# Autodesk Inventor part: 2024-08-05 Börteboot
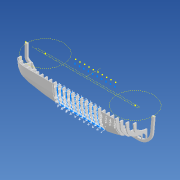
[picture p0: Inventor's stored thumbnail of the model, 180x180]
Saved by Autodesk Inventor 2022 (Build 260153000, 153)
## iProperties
Created: 2024-08
Part Number: 2024-08-05 Börteboot
Material: Generisch
Document SubType Name: Sheet Metal
Designer: i3meg
Density: 1 g/cm^3
Sheet Metal Rule: Standard_mm
Appearance: Vorgabe
Author: i3meg
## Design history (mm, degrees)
derived "2024-08-05 Börteboot.iam"
sketch "Skizze12"
  geometry: L1 (16, 30)-(12, 0) reference; L2 (12, 0)-(7.305, -13) reference; L3 (7.305, -13)-(-3.874, -24) reference; L4 (-3.874, -24)-(-19, -32) reference; L5 (16, 30)-(18, 30); L6 (18, 30)-(14.95, -0.547); L7 (14.95, -0.547)-(13.966, -0.365); L8 (13.966, -0.365)-(10.145, -13.968); L9 (10.145, -13.968)-(9.198, -13.646); L10 (9.198, -13.646)-(-1.833, -26.198); L11 (-1.833, -26.198)-(-2.513, -25.465); L12 (-2.513, -25.465)-(-17.597, -34.652); L13 (-49.5, -37.189)-(-49.5, -40.189); L14 (-49.5, -40.189)-(-47.5, -40.189); A1 r 117.777 centre (-11.284, -152.26) between (-17.597, -34.652) and (-47.5, -40.189); 1 further point
  constraints: 20 end point, 2 horizontal, 2 point on circle, 1 centre point, 1 vertical, 1 other
  dimensions: "d71" = 2 distance of L1.start L5.end; "d72" = 3 distance of L6.end L1.end; "d73" = 2 distance of L7.end L1.end; "d74" = 3 distance of L2.end L8.end; "d75" = 2 distance of L9.end L2.end; "d76" = 3 distance of L3.end L10.end; "d77" = 2 distance of L11.end L3.end; "d78" = 3 distance of L12.end L4.end; "d79" = 3 distance of L13.start L13.end; "d494" = 2 distance of L13.end L14.end
sketch "Skizze13"
  geometry: L1 (16, 35)-(12, 0) reference; L2 (12, 0)-(6, -17) reference; L3 (6, -17)-(-6.612, -32) reference; L4 (-6.612, -32)-(-25, -44) reference; L5 (16, 35)-(18, 35); L6 (18, 35)-(14.981, -0.341); L7 (14.981, -0.341)-(13.987, -0.227); L8 (13.987, -0.227)-(8.768, -18.156); L9 (8.768, -18.156)-(7.801, -17.87); L10 (7.801, -17.87)-(-4.671, -34.287); L11 (-4.671, -34.287)-(-5.623, -33.738); L12 (-5.623, -33.738)-(-23.89, -46.787); L13 (-65.5, -57.331)-(-65.5, -60.331); L14 (-65.5, -60.331)-(-63.5, -60.331); A1 r 220.96 centre (27.472, -261.695) between (-23.89, -46.787) and (-63.5, -60.331); 1 further point
  constraints: 20 end point, 2 point on circle, 1 centre point, 1 horizontal, 1 other
  dimensions: "d80" = 2 distance of L1.start L5.end; "d81" = 2 distance of L1.end L7.end; "d82" = 3 distance of L1.end L6.end; "d83" = 2 distance of L2.end L9.end; "d84" = 3 distance of L2.end L8.end; "d85" = 2 distance of L3.end L11.end; "d86" = 3 distance of L3.end L10.end; "d87" = 3 distance of L4.end L12.end; "d88" = 3 distance of L13.start L13.end; "d495" = 2 distance of L13.end L14.end
sketch "Skizze14"
  geometry: L1 (16, 40)-(12, 1) reference; L2 (12, 1)-(6, -17) reference; L3 (6, -17)-(-6, -34) reference; L4 (-6, -34)-(-24, -48) reference; L5 (0, 40)-(16, 40) reference; L6 (16, 40)-(18, 40); L7 (18, 40)-(14.984, 0.694); L8 (14.984, 0.694)-(13.99, 0.796); L9 (13.99, 0.796)-(8.846, -17.949); L10 (8.846, -17.949)-(7.897, -17.632); L11 (7.897, -17.632)-(-3.549, -35.73); L12 (-3.549, -35.73)-(-4.366, -35.153); L13 (-4.366, -35.153)-(-22.939, -50.806); L14 (-71.5, -66.872)-(-71.5, -69.872); L15 (-71.5, -69.872)-(-69.5, -69.872); A1 r 153.896 centre (11.315, -200.842) between (-22.939, -50.806) and (-69.5, -69.872); 1 further point
  constraints: 20 end point, 2 horizontal, 2 point on circle, 1 centre point, 1 vertical, 1 other
  dimensions: "d93" = 2 distance of L1.start L6.end; "d94" = 3 distance of L14.start L14.end; "d95" = 3 distance of L4.end L13.end; "d96" = 2 distance of L1.end L8.end; "d97" = 2 distance of L2.end L10.end; "d98" = 3 distance of L1.end L7.end; "d99" = 3 distance of L2.end L9.end; "d100" = 2 distance of L3.end L12.end; "d101" = 3 distance of L3.end L11.end; "d496" = 2 distance of L14.end L15.end
sketch "Skizze19"
  geometry: L1 (16, 40)-(12, -2) reference; L2 (12, -2)-(5, -20) reference; L3 (5, -20)-(-6, -38) reference; L4 (-6, -38)-(-23, -53) reference; L5 (16, 40)-(18, 40); L6 (18, 40)-(14.986, -2.284); L7 (14.986, -2.284)-(13.991, -2.19); L8 (13.991, -2.19)-(7.745, -21.211); L9 (7.745, -21.211)-(6.775, -20.923); L10 (6.775, -20.923)-(-3.62, -39.826); L11 (-3.62, -39.826)-(-4.6, -39.428); L12 (-4.6, -39.428)-(-21.466, -55.578); L13 (-73.5, -75.618)-(-73.5, -78.618); L14 (-73.5, -78.618)-(-71.5, -78.618); A1 r 207.905 centre (39.712, -254.278) between (-21.466, -55.578) and (-71.5, -78.618); 1 further point
  constraints: 20 end point, 2 horizontal, 2 point on circle, 1 centre point, 1 vertical, 1 other
  dimensions: "d114" = 2 distance of L1.start L5.end; "d115" = 3 distance of L13.start L13.end; "d116" = 2 distance of L1.end L7.end; "d117" = 3 distance of L1.end L6.end; "d118" = 2 distance of L2.end L9.end; "d119" = 3 distance of L2.end L8.end; "d120" = 2 distance of L3.end L11.end; "d121" = 3 distance of L3.end L10.end; "d122" = 3 distance of L4.end L12.end; "d497" = 2 distance of L13.end L14.end
sketch "Skizze23"
  geometry: L1 (16, 40)-(12, -3) reference; L2 (12, -3)-(6, -22) reference; L3 (6, -22)-(-5, -41) reference; L4 (-5, -41)-(-20, -57) reference; L5 (-73.5, -76.921)-(-73.5, -80.121); L6 (16, 40)-(18, 40); L7 (18, 40)-(14.986, -3.289); L8 (14.986, -3.289)-(13.988, -3.219); L9 (13.988, -3.219)-(8.888, -22.814); L10 (8.888, -22.814)-(7.919, -22.562); L11 (7.919, -22.562)-(-2.341, -42.39); L12 (-2.341, -42.39)-(-3.165, -41.796); L13 (-3.165, -41.796)-(-18.949, -59.81); L14 (-73.5, -80.121)-(-71.5, -80.121); A1 r 141.801 centre (4.877, -199.595) between (-18.949, -59.81) and (-71.5, -80.121); 1 further point
  constraints: 20 end point, 2 horizontal, 2 perpendicular, 2 point on circle, 1 centre point, 1 vertical, 1 other
  dimensions: "d142" = 3.2 distance of L5.start L5.end; "d143" = 2 distance of L1.start L6.end; "d144" = 2 distance of L1.end L8.end; "d145" = 3 distance of L1.end L7.end; "d146" = 2 distance of L2.end L10.end; "d147" = 3 distance of L2.end L9.end; "d148" = 2 distance of L3.end L12.end; "d149" = 3 distance of L3.end L11.end; "d150" = 3 distance of L13.end L4.end; "d498" = 2 distance of L5.end L14.end
sketch "Skizze24"
  geometry: L1 (16, 40)-(12, -4) reference; L2 (12, -4)-(6.5, -24) reference; L3 (6.5, -24)-(-4, -44) reference; L4 (-4, -44)-(-19, -61) reference; L5 (0, 40)-(16, 40) reference; L6 (16, 40)-(18, 40); L7 (18, 40)-(14.988, -4.272); L8 (14.988, -4.272)-(13.992, -4.181); L9 (13.992, -4.181)-(9.359, -24.909); L10 (9.359, -24.909)-(8.369, -24.713); L11 (8.369, -24.713)-(-1.344, -45.395); L12 (-1.344, -45.395)-(-2.229, -44.93); L13 (-2.229, -44.93)-(-17.749, -63.727); L14 (-73.5, -77.771)-(-73.5, -80.771); L15 (-73.5, -80.771)-(-71.5, -80.771); A1 r 219.794 centre (17.847, -277.683) between (-19, -61) and (-73.5, -77.771) reference; A2 r 202.647 centre (16.032, -263.538) between (-17.749, -63.727) and (-71.5, -80.771); 1 further point
  constraints: 20 end point, 2 horizontal, 2 point on circle, 1 centre point, 1 vertical
  dimensions: "d161" = 2 distance of L1.start L6.end; "d166" = 2 distance of L1.end L8.end; "d167" = 3 distance of L1.end L7.end; "d169" = 2 distance of L2.end L10.end; "d170" = 3 distance of L2.end L9.end; "d173" = 2 distance of L3.end L12.end; "d174" = 3 distance of L3.end L11.end; "d175" = 3 distance of L4.end L13.end; "d176" = 3 distance of L14.start L14.end; "d499" = 2 distance of L14.end L15.end
sketch "Skizze25"
  geometry: L1 (-2, -46)-(-18, -64) reference; L2 (7, -26)-(-2, -46) reference; L3 (12, -5)-(7, -26) reference; L4 (16, 40)-(12, -5) reference; L5 (16, 40)-(18, 40); L6 (18, 40)-(14.978, -5.364); L7 (14.978, -5.364)-(13.992, -5.177); L8 (13.992, -5.177)-(9.918, -26.695); L9 (9.918, -26.695)-(8.945, -26.465); L10 (8.945, -26.465)-(0.736, -47.231); L11 (0.736, -47.231)-(-0.176, -46.821); L12 (-0.176, -46.821)-(-16.767, -66.735); L13 (-73.5, -77.91)-(-73.5, -80.91); L14 (-73.5, -80.91)-(-71.5, -80.91); A1 r 433.619 centre (-150.935, 348.739) between (-73.5, -77.91) and (-18, -64) reference; A2 r 310.184 centre (-121.575, 225.206) between (-71.5, -80.91) and (-16.767, -66.735); 1 further point
  constraints: 20 end point, 2 horizontal, 2 point on circle, 1 centre point, 1 perpendicular, 1 vertical
  dimensions: "d189" = 2 distance of L4.start L5.end; "d190" = 3 distance of L13.start L13.end; "d191" = 2 distance of L3.start L7.end; "d192" = 3 distance of L3.start L6.end; "d193" = 2 distance of L2.start L9.end; "d194" = 3 distance of L2.start L8.end; "d195" = 2 distance of L1.start L11.end; "d196" = 3 distance of L1.start L10.end; "d197" = 3 distance of L1.end L12.end; "d500" = 2 distance of L13.end L14.end
sketch "Skizze27"
  geometry: L1 (16, 40)-(12, -6) reference; L2 (12, -6)-(7.5, -27) reference; L3 (7.5, -27)-(-1, -48) reference; L4 (-1, -48)-(-18, -66) reference; L5 (16, 40)-(18, 40); L6 (18, 40)-(14.981, -6.337); L7 (14.981, -6.337)-(13.992, -6.173); L8 (13.992, -6.173)-(10.417, -27.702); L9 (10.417, -27.702)-(9.43, -27.524); L10 (9.43, -27.524)-(1.773, -49.144); L11 (1.773, -49.144)-(0.854, -48.75); L12 (0.854, -48.75)-(-15.819, -68.06); L13 (-73.5, -77.945)-(-73.5, -80.945); A1 r 279.676 centre (-104.292, 200.031) between (-73.5, -77.945) and (-18, -66) reference; A2 r 259.061 centre (-100.77, 176.677) between (-73.5, -80.945) and (-15.819, -68.06); 1 further point
  constraints: 18 end point, 2 point on circle, 1 centre point, 1 horizontal, 1 perpendicular, 1 vertical
  dimensions: "d198" = 2 distance of L1.start L5.end; "d200" = 2 distance of L1.end L7.end; "d201" = 3 distance of L1.end L6.end; "d202" = 2 distance of L2.end L9.end; "d203" = 3 distance of L2.end L8.end; "d204" = 2 distance of L3.end L11.end; "d205" = 3 distance of L3.end L10.end; "d206" = 3 distance of L4.end L12.end; "d207" = 3 distance of L13.start L13.end
sketch "Skizze28"
  geometry: L1 (12, -7)-(16, 40) reference; L2 (8, -28)-(12, -7) reference; L3 (0, -49)-(8, -28) reference; L4 (-16, -67)-(0, -49) reference; L5 (-73.5, -77.992)-(-73.5, -80.992); L6 (16, 40)-(18, 40); L7 (18, 40)-(14.947, -7.561); L8 (14.947, -7.561)-(13.965, -7.374); L9 (13.965, -7.374)-(10.76, -29.176); L10 (10.76, -29.176)-(9.795, -28.883); L11 (9.795, -28.883)-(2.778, -50.133); L12 (2.778, -50.133)-(1.822, -49.824); L13 (1.822, -49.824)-(-13.372, -68.446); A1 r 171.355 centre (-76.452, 93.337) between (-73.5, -77.992) and (-16, -67) reference; A2 r 176.524 centre (-78.941, 95.448) between (-73.5, -80.992) and (-13.372, -68.446); 1 further point
  constraints: 18 end point, 2 point on circle, 1 centre point, 1 horizontal, 1 vertical
  dimensions: "d224" = 3 distance of L5.start L5.end; "d225" = 2 distance of L1.end L6.end; "d226" = 2 distance of L1.start L8.end; "d227" = 3 distance of L1.start L7.end; "d228" = 2 distance of L2.start L10.end; "d229" = 3 distance of L2.start L9.end; "d230" = 2 distance of L3.start L12.end; "d231" = 3 distance of L3.start L11.end; "d232" = 3 distance of L4.start L13.end
sketch "Skizze37"
  geometry: L1 (12, -7)-(16, 40) reference; L2 (8, -28)-(12, -7) reference; L3 (0, -49)-(8, -28) reference; L4 (-16, -67)-(0, -49) reference; L5 (-73.5, -77.992)-(-73.5, -80.992); L6 (16, 40)-(0, 40) reference; L7 (16, 40)-(18, 40); L8 (18, 40)-(14.985, -7.302); L9 (14.985, -7.302)-(13.993, -7.17); L10 (13.993, -7.17)-(10.905, -28.749); L11 (10.905, -28.749)-(9.955, -28.421); L12 (9.955, -28.421)-(2.818, -50.028); L13 (2.818, -50.028)-(1.868, -49.714); L14 (1.868, -49.714)-(-13.461, -68.598); A1 r 171.355 centre (-76.452, 93.337) between (-73.5, -77.992) and (-16, -67) reference; A2 r 170.875 centre (-77.466, 89.837) between (-73.5, -80.992) and (-13.461, -68.598); 1 further point
  constraints: 18 end point, 2 point on circle, 1 centre point, 1 horizontal, 1 perpendicular, 1 vertical
  dimensions: "d286" = 3 distance of L5.start L5.end; "d287" = 2 distance of L1.end L7.end; "d288" = 2 distance of L1.start L9.end; "d289" = 3 distance of L1.start L8.end; "d290" = 2 distance of L2.start L11.end; "d291" = 3 distance of L2.start L10.end; "d292" = 2 distance of L3.start L13.end; "d293" = 3 distance of L3.start L12.end; "d294" = 3 distance of L4.start L14.end
sketch "Skizze38"
  geometry: L1 (9.955, -28.421)-(2.818, -50.028); L2 (0, -49)-(8, -28); L3 (2.818, -50.028)-(1.868, -49.714); L4 (1.868, -49.714)-(-13.461, -68.598); L5 (-16, -67)-(0, -49); L6 (-73.5, -77.992)-(-73.5, -80.992); L7 (10.905, -28.749)-(9.955, -28.421); L8 (8, -28)-(12, -7); L9 (13.993, -7.17)-(10.905, -28.749); L10 (14.985, -7.302)-(13.993, -7.17); L11 (16, 40)-(0, 40); L12 (12, -7)-(16, 40); L13 (16, 40)-(18, 40); L14 (18, 40)-(14.985, -7.302); A1 r 170.875 centre (-77.466, 89.837) between (-73.5, -80.992) and (-13.461, -68.598); A2 r 171.355 centre (-76.452, 93.337) between (-73.5, -77.992) and (-16, -67); 1 further point
  constraints: 28 end point, 4 point on circle, 2 centre point, 1 horizontal, 1 perpendicular, 1 vertical
  dimensions: "d295" = 3 distance of L6.start L6.end; "d296" = 2 distance of L11.start L13.end; "d297" = 2 distance of L8.end L9.start; "d298" = 3 distance of L8.end L10.start; "d299" = 2 distance of L2.end L1.start; "d300" = 3 distance of L2.end L7.start; "d301" = 2 distance of L2.start L3.end; "d302" = 3 distance of L2.start L1.end; "d303" = 3 distance of L5.start L4.end
sketch "Skizze39"
  geometry: L1 (9.955, -28.421)-(2.818, -50.028); L2 (0, -49)-(8, -28); L3 (2.818, -50.028)-(1.868, -49.714); L4 (1.868, -49.714)-(-13.461, -68.598); L5 (-16, -67)-(0, -49); L6 (-73.5, -77.992)-(-73.5, -80.992); L7 (10.905, -28.749)-(9.955, -28.421); L8 (8, -28)-(12, -7); L9 (13.993, -7.17)-(10.905, -28.749); L10 (14.985, -7.302)-(13.993, -7.17); L11 (16, 40)-(0, 40); L12 (12, -7)-(16, 40); L13 (16, 40)-(18, 40); L14 (18, 40)-(14.985, -7.302); A1 r 170.875 centre (-77.466, 89.837) between (-73.5, -80.992) and (-13.461, -68.598); A2 r 171.355 centre (-76.452, 93.337) between (-73.5, -77.992) and (-16, -67); 1 further point
  constraints: 28 end point, 4 point on circle, 2 centre point, 1 horizontal, 1 perpendicular, 1 vertical
  dimensions: "d304" = 3 distance of L6.start L6.end; "d305" = 2 distance of L11.start L13.end; "d306" = 2 distance of L8.end L9.start; "d307" = 3 distance of L8.end L10.start; "d308" = 2 distance of L2.end L1.start; "d309" = 3 distance of L2.end L7.start; "d310" = 2 distance of L2.start L3.end; "d311" = 3 distance of L2.start L1.end; "d312" = 3 distance of L5.start L4.end
sketch "Skizze40"
  geometry: L1 (9.955, -28.421)-(2.818, -50.028); L2 (0, -49)-(8, -28); L3 (2.818, -50.028)-(1.868, -49.714); L4 (1.868, -49.714)-(-13.461, -68.598); L5 (-16, -67)-(0, -49); L6 (-73.5, -77.992)-(-73.5, -80.992); L7 (10.905, -28.749)-(9.955, -28.421); L8 (8, -28)-(12, -7); L9 (13.993, -7.17)-(10.905, -28.749); L10 (14.985, -7.302)-(13.993, -7.17); L11 (16, 40)-(0, 40); L12 (12, -7)-(16, 40); L13 (16, 40)-(18, 40); L14 (18, 40)-(14.985, -7.302); A1 r 170.875 centre (-77.466, 89.837) between (-73.5, -80.992) and (-13.461, -68.598); A2 r 171.355 centre (-76.452, 93.337) between (-73.5, -77.992) and (-16, -67); 1 further point
  constraints: 28 end point, 4 point on circle, 2 centre point, 1 horizontal, 1 perpendicular, 1 vertical
  dimensions: "d313" = 3 distance of L6.start L6.end; "d314" = 2 distance of L11.start L13.end; "d315" = 2 distance of L8.end L9.start; "d316" = 3 distance of L8.end L10.start; "d317" = 2 distance of L2.end L1.start; "d318" = 3 distance of L2.end L7.start; "d319" = 2 distance of L2.start L3.end; "d320" = 3 distance of L2.start L1.end; "d321" = 3 distance of L5.start L4.end
sketch "Skizze41"
  geometry: L1 (9.955, -28.421)-(2.818, -50.028); L2 (0, -49)-(8, -28); L3 (2.818, -50.028)-(1.868, -49.714); L4 (1.868, -49.714)-(-13.461, -68.598); L5 (-16, -67)-(0, -49); L6 (-73.5, -77.992)-(-73.5, -80.992); L7 (10.905, -28.749)-(9.955, -28.421); L8 (8, -28)-(12, -7); L9 (13.993, -7.17)-(10.905, -28.749); L10 (14.985, -7.302)-(13.993, -7.17); L11 (16, 40)-(0, 40); L12 (12, -7)-(16, 40); L13 (16, 40)-(18, 40); L14 (18, 40)-(14.985, -7.302); A1 r 170.875 centre (-77.466, 89.837) between (-73.5, -80.992) and (-13.461, -68.598); A2 r 171.355 centre (-76.452, 93.337) between (-73.5, -77.992) and (-16, -67); 1 further point
  constraints: 28 end point, 4 point on circle, 2 centre point, 1 horizontal, 1 perpendicular, 1 vertical
  dimensions: "d322" = 3 distance of L6.start L6.end; "d323" = 2 distance of L11.start L13.end; "d324" = 2 distance of L8.end L9.start; "d325" = 3 distance of L8.end L10.start; "d326" = 2 distance of L2.end L1.start; "d327" = 3 distance of L2.end L7.start; "d328" = 2 distance of L2.start L3.end; "d329" = 3 distance of L2.start L1.end; "d330" = 3 distance of L5.start L4.end
sketch "Skizze42"
  geometry: L1 (9.955, -28.421)-(2.818, -50.028); L2 (0, -49)-(8, -28); L3 (2.818, -50.028)-(1.868, -49.714); L4 (1.868, -49.714)-(-13.461, -68.598); L5 (-16, -67)-(0, -49); L6 (-73.5, -77.992)-(-73.5, -80.992); L7 (10.905, -28.749)-(9.955, -28.421); L8 (8, -28)-(12, -7); L9 (13.993, -7.17)-(10.905, -28.749); L10 (14.985, -7.302)-(13.993, -7.17); L11 (16, 40)-(0, 40); L12 (12, -7)-(16, 40); L13 (16, 40)-(18, 40); L14 (18, 40)-(14.985, -7.302); A1 r 170.875 centre (-77.466, 89.837) between (-73.5, -80.992) and (-13.461, -68.598); A2 r 171.355 centre (-76.452, 93.337) between (-73.5, -77.992) and (-16, -67); 1 further point
  constraints: 28 end point, 4 point on circle, 2 centre point, 1 horizontal, 1 perpendicular, 1 vertical
  dimensions: "d331" = 3 distance of L6.start L6.end; "d332" = 2 distance of L11.start L13.end; "d333" = 2 distance of L8.end L9.start; "d334" = 3 distance of L8.end L10.start; "d335" = 2 distance of L2.end L1.start; "d336" = 3 distance of L2.end L7.start; "d337" = 2 distance of L2.start L3.end; "d338" = 3 distance of L2.start L1.end; "d339" = 3 distance of L5.start L4.end
sketch "Skizze43"
  geometry: L1 (9.955, -28.421)-(2.818, -50.028); L2 (0, -49)-(8, -28); L3 (2.818, -50.028)-(1.868, -49.714); L4 (1.868, -49.714)-(-13.461, -68.598); L5 (-16, -67)-(0, -49); L6 (-73.5, -77.992)-(-73.5, -80.992); L7 (10.905, -28.749)-(9.955, -28.421); L8 (8, -28)-(12, -7); L9 (13.993, -7.17)-(10.905, -28.749); L10 (14.985, -7.302)-(13.993, -7.17); L11 (16, 40)-(0, 40); L12 (12, -7)-(16, 40); L13 (16, 40)-(18, 40); L14 (18, 40)-(14.985, -7.302); A1 r 170.875 centre (-77.466, 89.837) between (-73.5, -80.992) and (-13.461, -68.598); A2 r 171.355 centre (-76.452, 93.337) between (-73.5, -77.992) and (-16, -67); 1 further point
  constraints: 28 end point, 4 point on circle, 2 centre point, 1 horizontal, 1 perpendicular, 1 vertical
  dimensions: "d340" = 3 distance of L6.start L6.end; "d341" = 2 distance of L11.start L13.end; "d342" = 2 distance of L8.end L9.start; "d343" = 3 distance of L8.end L10.start; "d344" = 2 distance of L2.end L1.start; "d345" = 3 distance of L2.end L7.start; "d346" = 2 distance of L2.start L3.end; "d347" = 3 distance of L2.start L1.end; "d348" = 3 distance of L5.start L4.end
sketch "Skizze44"
  geometry: L1 (9.955, -28.421)-(2.818, -50.028); L2 (0, -49)-(8, -28); L3 (2.818, -50.028)-(1.868, -49.714); L4 (1.868, -49.714)-(-13.461, -68.598); L5 (-16, -67)-(0, -49); L6 (-73.5, -77.992)-(-73.5, -80.992); L7 (10.905, -28.749)-(9.955, -28.421); L8 (8, -28)-(12, -7); L9 (13.993, -7.17)-(10.905, -28.749); L10 (14.985, -7.302)-(13.993, -7.17); L11 (16, 40)-(0, 40); L12 (12, -7)-(16, 40); L13 (16, 40)-(18, 40); L14 (18, 40)-(14.985, -7.302); A1 r 170.875 centre (-77.466, 89.837) between (-73.5, -80.992) and (-13.461, -68.598); A2 r 171.355 centre (-76.452, 93.337) between (-73.5, -77.992) and (-16, -67); 1 further point
  constraints: 28 end point, 4 point on circle, 2 centre point, 1 horizontal, 1 perpendicular, 1 vertical
  dimensions: "d349" = 3 distance of L6.start L6.end; "d350" = 2 distance of L11.start L13.end; "d351" = 2 distance of L8.end L9.start; "d352" = 3 distance of L8.end L10.start; "d353" = 2 distance of L2.end L1.start; "d354" = 3 distance of L2.end L7.start; "d355" = 2 distance of L2.start L3.end; "d356" = 3 distance of L2.start L1.end; "d357" = 3 distance of L5.start L4.end
sketch "Skizze45"
  geometry: L1 (9.955, -28.421)-(2.818, -50.028); L2 (0, -49)-(8, -28); L3 (2.818, -50.028)-(1.868, -49.714); L4 (1.868, -49.714)-(-13.461, -68.598); L5 (-16, -67)-(0, -49); L6 (-73.5, -77.992)-(-73.5, -80.992); L7 (10.905, -28.749)-(9.955, -28.421); L8 (8, -28)-(12, -7); L9 (13.993, -7.17)-(10.905, -28.749); L10 (14.985, -7.302)-(13.993, -7.17); L11 (16, 40)-(0, 40); L12 (12, -7)-(16, 40); L13 (16, 40)-(18, 40); L14 (18, 40)-(14.985, -7.302); A1 r 170.875 centre (-77.466, 89.837) between (-73.5, -80.992) and (-13.461, -68.598); A2 r 171.355 centre (-76.452, 93.337) between (-73.5, -77.992) and (-16, -67); 1 further point
  constraints: 28 end point, 4 point on circle, 2 centre point, 1 horizontal, 1 perpendicular, 1 vertical
  dimensions: "d358" = 3 distance of L6.start L6.end; "d359" = 2 distance of L11.start L13.end; "d360" = 2 distance of L8.end L9.start; "d361" = 3 distance of L8.end L10.start; "d362" = 2 distance of L2.end L1.start; "d363" = 3 distance of L2.end L7.start; "d364" = 2 distance of L2.start L3.end; "d365" = 3 distance of L2.start L1.end; "d366" = 3 distance of L5.start L4.end
sketch "Skizze46"
  geometry: L1 (9.955, -28.421)-(2.818, -50.028); L2 (0, -49)-(8, -28); L3 (2.818, -50.028)-(1.868, -49.714); L4 (1.868, -49.714)-(-13.461, -68.598); L5 (-16, -67)-(0, -49); L6 (-73.5, -77.992)-(-73.5, -80.992); L7 (10.905, -28.749)-(9.955, -28.421); L8 (8, -28)-(12, -7); L9 (13.993, -7.17)-(10.905, -28.749); L10 (14.985, -7.302)-(13.993, -7.17); L11 (16, 40)-(0, 40); L12 (12, -7)-(16, 40); L13 (16, 40)-(18, 40); L14 (18, 40)-(14.985, -7.302); A1 r 170.875 centre (-77.466, 89.837) between (-73.5, -80.992) and (-13.461, -68.598); A2 r 171.355 centre (-76.452, 93.337) between (-73.5, -77.992) and (-16, -67); 1 further point
  constraints: 28 end point, 4 point on circle, 2 centre point, 1 horizontal, 1 perpendicular, 1 vertical
  dimensions: "d367" = 3 distance of L6.start L6.end; "d368" = 2 distance of L11.start L13.end; "d369" = 2 distance of L8.end L9.start; "d370" = 3 distance of L8.end L10.start; "d371" = 2 distance of L2.end L1.start; "d372" = 3 distance of L2.end L7.start; "d373" = 2 distance of L2.start L3.end; "d374" = 3 distance of L2.start L1.end; "d375" = 3 distance of L5.start L4.end
sketch "Skizze47"
  geometry: L1 (10.151, -27.835)-(2.749, -50.245); L2 (0.018, -49.003)-(8.163, -27.619); L3 (2.749, -50.245)-(1.791, -49.928); L4 (1.791, -49.928)-(-13.461, -68.598); L5 (-16, -67)-(0.018, -49.003); L6 (-73.5, -77.992)-(-73.5, -80.992); L7 (11.127, -28.079)-(10.151, -27.835); L8 (8.163, -27.619)-(11.994, -6.262); L9 (13.986, -6.445)-(11.127, -28.079); L10 (14.987, -6.472)-(13.986, -6.445); L11 (15.923, 39.786)-(-0.077, 39.786); L12 (11.994, -6.262)-(15.923, 39.786); L13 (15.923, 39.786)-(17.923, 39.786); L14 (17.923, 39.786)-(14.987, -6.472); A1 r 170.875 centre (-77.466, 89.837) between (-73.5, -80.992) and (-13.461, -68.598); A2 r 171.355 centre (-76.452, 93.337) between (-73.5, -77.992) and (-16, -67); 1 further point
  constraints: 28 end point, 4 point on circle, 2 centre point, 1 horizontal, 1 perpendicular, 1 vertical
  dimensions: "d376" = 3 distance of L6.start L6.end; "d377" = 2 distance of L11.start L13.end; "d378" = 2 distance of L8.end L9.start; "d379" = 3 distance of L8.end L10.start; "d380" = 2 distance of L2.end L1.start; "d381" = 3 distance of L2.end L7.start; "d382" = 2 distance of L2.start L3.end; "d383" = 3 distance of L2.start L1.end; "d384" = 3 distance of L5.start L4.end
sketch "Skizze48"
  geometry: L1 (12, -5)-(16, 40) reference; L2 (7, -26)-(12, -5) reference; L3 (-1, -46)-(7, -26) reference; L4 (-17, -65)-(-1, -46) reference; L5 (-73.5, -77.921)-(-73.5, -80.921); L6 (0, 40)-(16, 40) reference; L7 (16, 40)-(18, 40); L8 (18, 40)-(14.976, -5.383); L9 (14.976, -5.383)-(13.983, -5.258); L10 (13.983, -5.258)-(9.918, -26.697); L11 (9.918, -26.697)-(8.961, -26.393); L12 (8.961, -26.393)-(1.755, -47.189); L13 (1.755, -47.189)-(0.806, -46.86); L14 (0.806, -46.86)-(-15.718, -67.712); L15 (-73.5, -80.921)-(-71.5, -80.921); A1 r 433.619 centre (-141.7, 350.301) between (-73.5, -77.921) and (-17, -65) reference; A2 r 288.501 centre (-109.755, 205.033) between (-71.5, -80.921) and (-15.718, -67.712); 1 further point
  constraints: 20 end point, 2 horizontal, 2 point on circle, 1 centre point, 1 perpendicular, 1 vertical
  dimensions: "d425" = 3 distance of L5.start L5.end; "d426" = 2 distance of L1.end L7.end; "d427" = 2 distance of L1.start L9.end; "d428" = 3 distance of L1.start L8.end; "d429" = 2 distance of L2.start L11.end; "d430" = 3 distance of L2.start L10.end; "d431" = 2 distance of L3.start L13.end; "d432" = 3 distance of L3.start L12.end; "d433" = 3 distance of L4.start L14.end; "d501" = 2 distance of L5.end L15.end
sketch "Skizze49"
  geometry: L1 (12, -4)-(16, 40) reference; L2 (6.5, -24)-(12, -4) reference; L3 (-3, -44)-(6.5, -24) reference; L4 (-18, -61)-(-3, -44) reference; L5 (-73.5, -77.772)-(-73.5, -80.772); L6 (16, 40)-(18, 40); L7 (18, 40)-(14.988, -4.272); L8 (14.988, -4.272)-(13.992, -4.181); L9 (13.992, -4.181)-(9.365, -24.889); L10 (9.365, -24.889)-(8.428, -24.532); L11 (8.428, -24.532)-(-0.257, -45.215); L12 (-0.257, -45.215)-(-1.132, -44.714); L13 (-1.132, -44.714)-(-16.717, -63.712); L14 (-73.5, -80.772)-(-71.5, -80.772); A1 r 219.794 centre (17.278, -277.944) between (-18, -61) and (-73.5, -77.772) reference; A2 r 235.378 centre (25.356, -295.299) between (-16.717, -63.712) and (-71.5, -80.772); 1 further point
  constraints: 20 end point, 2 horizontal, 2 point on circle, 1 centre point, 1 vertical
  dimensions: "d434" = 3 distance of L5.start L5.end; "d435" = 2 distance of L1.end L6.end; "d436" = 2 distance of L1.start L8.end; "d437" = 3 distance of L1.start L7.end; "d438" = 2 distance of L2.start L10.end; "d439" = 3 distance of L2.start L9.end; "d440" = 3 distance of L13.end L4.start; "d450" = 2 distance of L3.start L12.end; "d451" = 3 distance of L3.start L11.end; "d502" = 2 distance of L5.end L14.end
sketch "Skizze51"
  geometry: L1 (12, -3)-(16, 40) reference; L2 (5, -22)-(12, -3) reference; L3 (-5, -41)-(5, -22) reference; L4 (-20, -57)-(-5, -41) reference; L5 (-73.5, -76.936)-(-73.5, -79.936); L6 (16, 40)-(18, 40); L7 (18, 40)-(14.987, -3.278); L8 (14.987, -3.278)-(13.991, -3.185); L9 (13.991, -3.185)-(7.751, -23.196); L10 (7.751, -23.196)-(6.845, -22.771); L11 (6.845, -22.771)-(-2.328, -42.363); L12 (-2.328, -42.363)-(-3.246, -41.961); L13 (-3.246, -41.961)-(-18.862, -59.776); L14 (-73.5, -79.936)-(-71.5, -79.936); A1 r 155.061 centre (9.356, -212.248) between (-18.862, -59.776) and (-71.5, -79.936); 1 further point
  constraints: 20 end point, 2 horizontal, 2 point on circle, 1 centre point, 1 perpendicular, 1 vertical, 1 other
  dimensions: "d452" = 3 distance of L5.start L5.end; "d453" = 2 distance of L1.end L6.end; "d454" = 3 distance of L4.start L13.end; "d455" = 2 distance of L1.start L8.end; "d456" = 3 distance of L1.start L7.end; "d457" = 2 distance of L2.start L10.end; "d458" = 3 distance of L2.start L9.end; "d459" = 2 distance of L3.start L12.end; "d460" = 3 distance of L3.start L11.end; "d503" = 2 distance of L5.end L14.end
sketch "Skizze52"
  geometry: L1 (12, -2)-(16, 40) reference; L2 (3, -20)-(12, -2) reference; L3 (-8, -38)-(3, -20) reference; L4 (-23, -53)-(-8, -38) reference; L5 (-73.5, -75.618)-(-73.5, -78.618); L6 (3, -20)-(-8, -38) reference; L7 (16, 40)-(18, 40); L8 (0, 40)-(0, 0) reference; L9 (18, 40)-(14.986, -2.284); L10 (14.986, -2.284)-(13.991, -2.19); L11 (13.991, -2.19)-(5.702, -21.304); L12 (5.702, -21.304)-(4.782, -20.908); L13 (4.782, -20.908)-(-5.475, -39.62); L14 (-5.475, -39.62)-(-6.349, -39.128); L15 (-6.349, -39.128)-(-22.303, -55.918); L16 (-73.5, -78.618)-(-71.5, -78.618); A1 r 114.523 centre (-0.282, -168.304) between (-22.303, -55.918) and (-71.5, -78.618); 1 further point
  constraints: 20 end point, 2 point on circle, 1 centre point, 1 horizontal, 1 perpendicular, 1 vertical, 1 other
  dimensions: "d461" = 3 distance of L5.start L5.end; "d466" = 2 distance of L1.end L7.end; "d467" = 2 distance of L1.start L10.end; "d468" = 3 distance of L1.start L9.end; "d469" = 2 distance of L2.start L12.end; "d470" = 3 distance of L2.start L11.end; "d471" = 2 distance of L3.start L14.end; "d472" = 3 distance of L3.start L13.end; "d473" = 3 distance of L4.start L15.end; "d504" = 2 distance of L5.end L16.end
feature "Erhebung15" sketch "Skizze48", "Skizze49", "Skizze51", "Skizze52" dims "d505" = 0, "d506" = 90 deg, "d507" = 0, "d508" = 90 deg, "d509" = 0, "d510" = 90 deg, "d511" = 0, "d512" = 90 deg
feature "Erhebung16" dims "d513" = 0, "d514" = 90 deg, "d515" = 0, "d516" = 90 deg, "d517" = 0, "d518" = 90 deg, "d519" = 0, "d520" = 90 deg, "d521" = 0, "d522" = 90 deg, "d523" = 0, "d524" = 90 deg, "d525" = 0, "d526" = 90 deg, "d527" = 0, "d528" = 90 deg, "d529" = 0, "d530" = 90 deg, "d531" = 0, "d532" = 90 deg
node "Volumenkörper1"
node "2024-08-05 Börteboot Kiel.ipt:1" dims "d0" = 10
sketch "Skizze4"
  geometry: L1 (670.933, 9)-(670.933, 0) reference; L2 (57, 9)-(57, 0) reference; L3 (590, 0)-(57, 0) reference; L4 (590, 9)-(590, 0) reference; L5 (57, 9)-(590, 9) reference; L6 (35, 0)-(590, 0) reference; L7 (312.5, 0)-(312.5, 81.559) reference; C1 r 95 at (102.5, 4.5) reference; C2 r 95 at (569.5, 4.5) reference; 1 further point
node "2024-08-05 Börteboot Spanten.ipt:1" dims "d0" = 10
other parameters: "Stärke" = 0.5, "Biegeradius" = 0.5 (= Stärke), "BreiteBiegungsfreistellung" = 0.5 (= Stärke), "TiefeBiegungsfreistellung" = 0.25 (= 0.5 x Stärke), "GrößeEckenfreistellung" = 2 (= 4 x Stärke), "SeamGap" = 0.01, "MinimalRest" = 1 (= 2 x Stärke), "Übergangsradius" = 0.5 (= Biegeradius), "JacobiRadiusGröße" = 0.5 (= Biegeradius), "Abstandsgröße" = 0.5 (= Stärke)
